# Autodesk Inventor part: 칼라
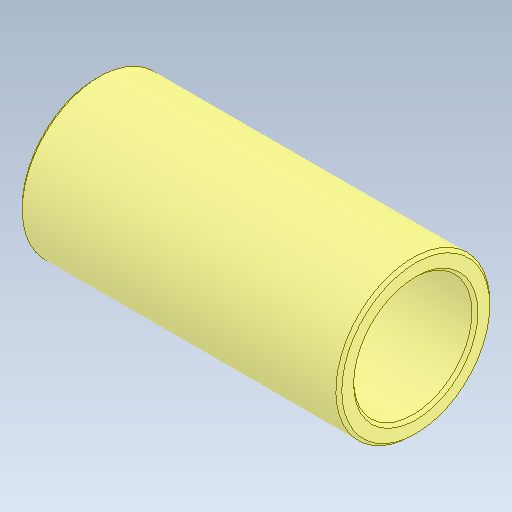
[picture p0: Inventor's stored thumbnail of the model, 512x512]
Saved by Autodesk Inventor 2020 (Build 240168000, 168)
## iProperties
Created: 2024-09
Part Number: 칼라
Material: 강철, 연강
Document SubType Name: Modeling
Designer: oem
Density: 7.85 g/cm^3
Appearance: 기본값
Author: jhkim
Sending System: Autodesk Inventor 2025
Preprocessor: ST-DEVELOPER v20
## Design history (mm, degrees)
feature "솔리드1"
node "솔리드2"
